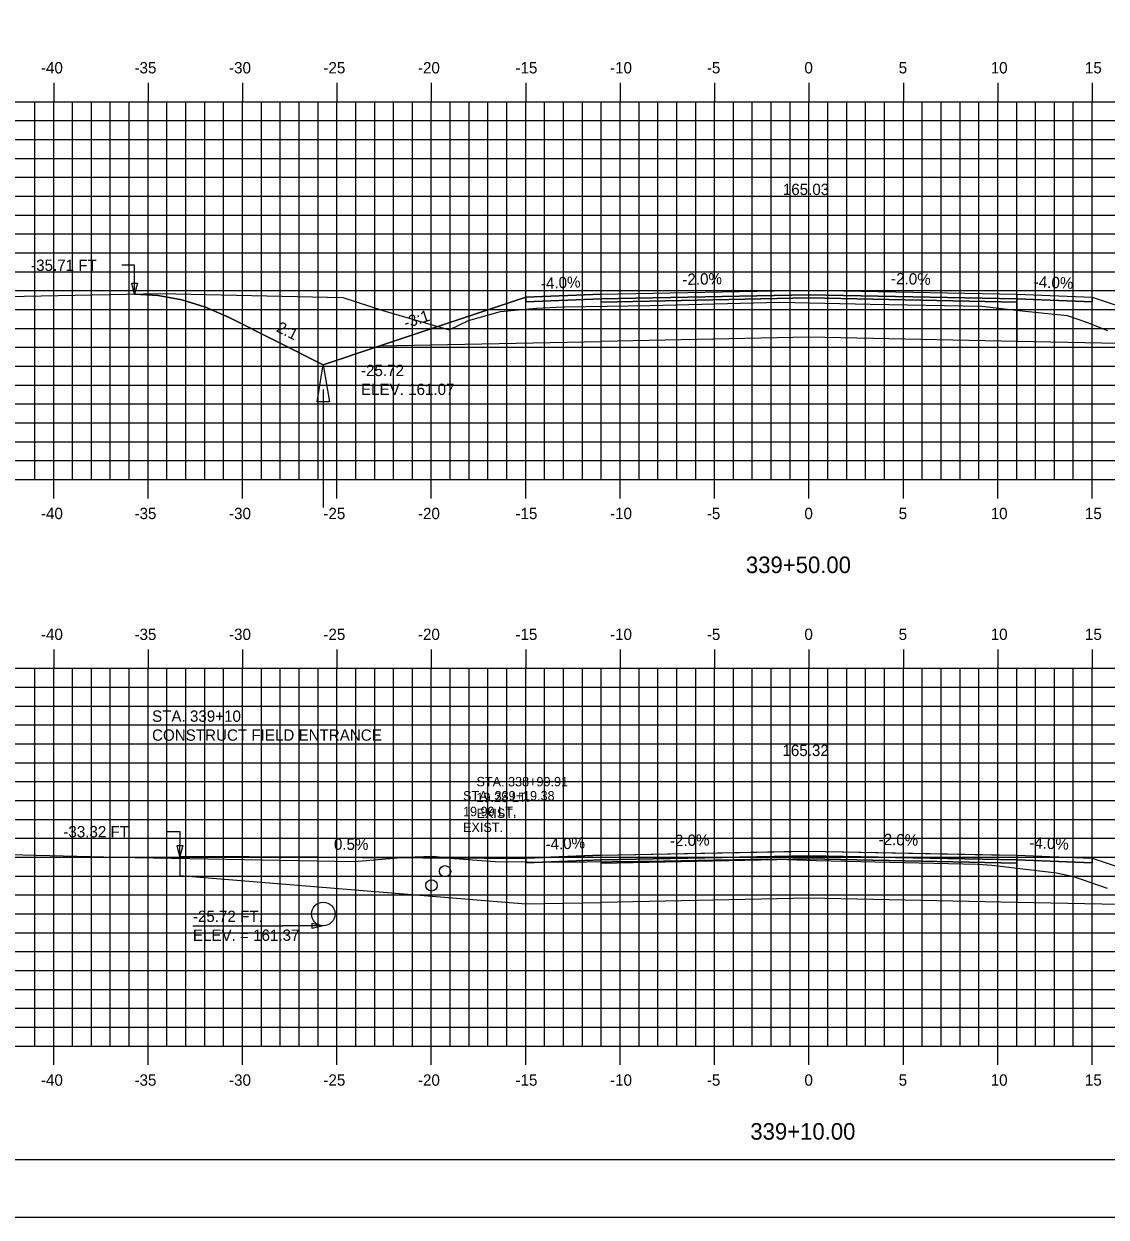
# Model space of a CAD drawing. Extents: x 1142755 to 1142925, y 608981 to 609091.
# Drawn here: x 1142796.2 to 1142853.5, y 608981.3 to 609044.5 of the extents above; entities that cross this region are included whole.
import ezdxf

# ---------------------------------------------------------------- set-up
doc = ezdxf.new("R2010")
doc.units = 0
for name, color, linetype in [('ANNOTATION', 7, 'Continuous'), ('BORDER', 7, 'Continuous'), ('D_Drainage_Culvert', 7, 'Continuous'), ('D_Drainage_Ditch_Line', 7, 'Continuous'), ('D_Roadway_Centerline', 7, 'Continuous'), ('D_Roadway_Centerline_Text', 7, 'Continuous'), ('D_Roadway_Edge_Shoulder', 7, 'Continuous'), ('D_Roadway_Edge_TW', 7, 'Continuous'), ('D_Roadway_Pavement', 7, 'Continuous'), ('D_Roadway_SlopeLines', 7, 'Continuous'), ('D_Roadway_SubGrade', 7, 'Continuous'), ('D_Text_Monospaced', 7, 'Continuous'), ('D_Text_Standard', 7, 'Continuous'), ('H_V ANNOTATION', 7, 'Continuous'), ('MAJOR', 7, 'Continuous'), ('MINOR', 7, 'Continuous'), ('PLOT BOUNDARY', 7, 'Continuous'), ('S_Drainage_Invert', 7, 'Continuous'), ('S_Roadway_Centerline', 7, 'Continuous')]:
    doc.layers.add(name, color=color, linetype=linetype)

msp = doc.modelspace()

# ---------------------------------------------------------------- linework, layer by layer
for points in [[(1142802.095, 609030.152), (1142803.345, 609030.075), (1142804.595, 609029.841), (1142805.845, 609029.451), (1142807.095, 609028.904), (1142812.085, 609026.409), (1142815.085, 609027.409), (1142822.809, 609029.983), (1142822.81, 609029.983), (1142826.81, 609030.143), (1142837.81, 609030.363), (1142848.81, 609030.143), (1142852.81, 609029.983), (1142860.533, 609027.409), (1142863.533, 609026.409), (1142866.262, 609027.773), (1142867.512, 609028.319), (1142868.762, 609028.709), (1142870.012, 609028.941), (1142871.262, 609029.016)], [(1142804.493, 609000.369), (1142820.615, 609000.288), (1142822.81, 609000.277), (1142823.29, 609000.296), (1142826.81, 609000.437), (1142836.49, 609000.631), (1142837.81, 609000.657), (1142847.49, 609000.464), (1142848.81, 609000.437), (1142852.33, 609000.296), (1142852.81, 609000.277), (1142859.606, 608998.012)]]:
    msp.add_lwpolyline(points)
at = {"layer": 'BORDER'}
msp.add_lwpolyline([(1142762.81, 608984.335), (1142922.81, 608984.335), (1142922.81, 609089.335), (1142762.81, 609089.335)], close=True, dxfattribs=at)
at = {"layer": 'D_Drainage_Culvert'}
msp.add_circle((1142812.086, 608997.328), 0.625, dxfattribs=at)
at = {"layer": 'D_Drainage_Ditch_Line'}
msp.add_line((1142812.085, 609025.097), (1142812.085, 609018.853), dxfattribs=at)
msp.add_lwpolyline([(1142812.413, 609024.44), (1142811.757, 609024.44), (1142812.085, 609026.409)], close=True, dxfattribs=at)
at = {"layer": 'D_Roadway_Edge_Shoulder'}
for points in [[(1142826.81, 609030.143), (1142822.81, 609029.983), (1142822.81, 609029.733), (1142826.81, 609029.893)], [(1142848.81, 609030.143), (1142852.81, 609029.983), (1142852.81, 609029.733), (1142848.81, 609029.893)], [(1142826.81, 609000.437), (1142822.81, 609000.277), (1142822.81, 609000.027), (1142826.81, 609000.187)], [(1142848.81, 609000.437), (1142852.81, 609000.277), (1142852.81, 609000.027), (1142848.81, 609000.187)]]:
    msp.add_lwpolyline(points, close=True, dxfattribs=at)
at = {"layer": 'D_Roadway_Edge_TW'}
for points in [[(1142826.81, 609029.893), (1142826.81, 609030.143), (1142837.81, 609030.363), (1142848.81, 609030.143), (1142848.81, 609029.893), (1142837.81, 609030.113)], [(1142826.81, 609000.187), (1142826.81, 609000.437), (1142837.81, 609000.657), (1142848.81, 609000.437), (1142848.81, 609000.187), (1142837.81, 609000.407)]]:
    msp.add_lwpolyline(points, close=True, dxfattribs=at)
at = {"layer": 'D_Roadway_Pavement'}
for points in [[(1142826.81, 609029.727), (1142826.81, 609029.893), (1142837.81, 609030.113), (1142848.81, 609029.893), (1142848.81, 609029.727), (1142837.81, 609029.947)], [(1142826.81, 609000.02), (1142826.81, 609000.187), (1142837.81, 609000.407), (1142848.81, 609000.187), (1142848.81, 609000.021), (1142837.81, 609000.241)]]:
    msp.add_lwpolyline(points, close=True, dxfattribs=at)
at = {"layer": 'D_Roadway_SlopeLines'}
for points in [[(1142812.085, 609026.409), (1142807.095, 609028.904), (1142805.845, 609029.451), (1142804.595, 609029.841), (1142803.345, 609030.075), (1142802.095, 609030.152)], [(1142815.085, 609027.409), (1142812.085, 609026.409)]]:
    msp.add_lwpolyline(points, dxfattribs=at)
at = {"layer": 'D_Roadway_SubGrade'}
for points in [[(1142826.81, 609029.727), (1142826.81, 609029.893), (1142822.81, 609029.733), (1142822.81, 609029.983), (1142822.809, 609029.983), (1142815.085, 609027.409), (1142826.81, 609027.643)], [(1142826.81, 609027.643), (1142826.81, 609029.727), (1142837.81, 609029.947), (1142848.81, 609029.727), (1142848.81, 609027.643), (1142837.81, 609027.863)], [(1142848.81, 609029.727), (1142848.81, 609029.893), (1142852.81, 609029.733), (1142852.81, 609029.983), (1142852.81, 609029.983), (1142860.533, 609027.409), (1142848.81, 609027.643)], [(1142804.493, 608999.369), (1142822.81, 608997.857), (1142826.81, 608997.937), (1142826.81, 609000.02), (1142826.81, 609000.187), (1142822.81, 609000.027), (1142822.81, 609000.277), (1142804.493, 609000.369)], [(1142826.81, 608997.937), (1142826.81, 609000.02), (1142837.81, 609000.241), (1142848.81, 609000.021), (1142848.81, 608997.937), (1142837.81, 608998.157)], [(1142848.81, 609000.021), (1142848.81, 609000.187), (1142852.81, 609000.027), (1142852.81, 609000.277), (1142852.81, 609000.277), (1142860.533, 608997.703), (1142848.81, 608997.937)]]:
    msp.add_lwpolyline(points, close=True, dxfattribs=at)
at = {"layer": 'D_Text_Standard'}
msp.add_line((1142805.182, 608996.703), (1142809.94, 608996.703), dxfattribs=at)
for points in [[(1142802.095, 609030.154), (1142802.097, 609031.677), (1142801.417, 609031.677)], [(1142804.493, 609000.369), (1142804.5, 609001.684), (1142803.82, 609001.684)], [(1142812.086, 608996.703), (1142810.62, 608996.703), (1142809.94, 608996.703)]]:
    msp.add_lwpolyline(points, dxfattribs=at)
for points in [[(1142802.095, 609030.154), (1142801.95, 609030.736), (1142802.241, 609030.736)], [(1142804.493, 609000.369), (1142804.35, 609000.952), (1142804.641, 609000.95)], [(1142812.086, 608996.703), (1142811.504, 608996.557), (1142811.504, 608996.848)]]:
    msp.add_lwpolyline(points, close=True, dxfattribs=at)
at = {"layer": 'MAJOR'}
for p, q in [((1142797.81, 609041.337), (1142797.81, 609040.335)), ((1142802.81, 609041.337), (1142802.81, 609040.335)), ((1142807.81, 609041.337), (1142807.81, 609040.335)), ((1142812.81, 609041.337), (1142812.81, 609040.335)), ((1142817.81, 609041.337), (1142817.81, 609040.335)), ((1142822.81, 609041.337), (1142822.81, 609040.335)), ((1142827.81, 609041.337), (1142827.81, 609040.335)), ((1142832.81, 609041.337), (1142832.81, 609040.335)), ((1142837.81, 609041.337), (1142837.81, 609040.335)), ((1142842.81, 609041.337), (1142842.81, 609040.335)), ((1142847.81, 609041.337), (1142847.81, 609040.335)), ((1142852.81, 609041.337), (1142852.81, 609040.335)), ((1142767.81, 609040.335), (1142907.81, 609040.335)), ((1142767.81, 609040.335), (1142907.81, 609040.335)), ((1142797.81, 609020.335), (1142797.81, 609040.335)), ((1142802.81, 609020.335), (1142802.81, 609040.335)), ((1142807.81, 609020.335), (1142807.81, 609040.335)), ((1142812.81, 609020.335), (1142812.81, 609040.335)), ((1142817.81, 609020.335), (1142817.81, 609040.335)), ((1142822.81, 609020.335), (1142822.81, 609040.335)), ((1142827.81, 609020.335), (1142827.81, 609040.335)), ((1142832.81, 609020.335), (1142832.81, 609040.335)), ((1142837.81, 609020.335), (1142837.81, 609040.335)), ((1142842.81, 609020.335), (1142842.81, 609040.335)), ((1142847.81, 609020.335), (1142847.81, 609040.335)), ((1142852.81, 609020.335), (1142852.81, 609040.335)), ((1142767.81, 609035.335), (1142907.81, 609035.335)), ((1142767.81, 609030.335), (1142907.81, 609030.335)), ((1142767.81, 609025.335), (1142907.81, 609025.335)), ((1142767.81, 609020.335), (1142907.81, 609020.335)), ((1142767.81, 609020.335), (1142907.81, 609020.335)), ((1142797.81, 609019.333), (1142797.81, 609020.335)), ((1142802.81, 609019.333), (1142802.81, 609020.335)), ((1142807.81, 609019.333), (1142807.81, 609020.335)), ((1142812.81, 609019.333), (1142812.81, 609020.335)), ((1142817.81, 609019.333), (1142817.81, 609020.335)), ((1142822.81, 609019.333), (1142822.81, 609020.335)), ((1142827.81, 609019.333), (1142827.81, 609020.335)), ((1142832.81, 609019.333), (1142832.81, 609020.335)), ((1142837.81, 609019.333), (1142837.81, 609020.335)), ((1142842.81, 609019.333), (1142842.81, 609020.335)), ((1142847.81, 609019.333), (1142847.81, 609020.335)), ((1142852.81, 609019.333), (1142852.81, 609020.335)), ((1142797.81, 609011.337), (1142797.81, 609010.335)), ((1142802.81, 609011.337), (1142802.81, 609010.335)), ((1142807.81, 609011.337), (1142807.81, 609010.335)), ((1142812.81, 609011.337), (1142812.81, 609010.335)), ((1142817.81, 609011.337), (1142817.81, 609010.335)), ((1142822.81, 609011.337), (1142822.81, 609010.335)), ((1142827.81, 609011.337), (1142827.81, 609010.335)), ((1142832.81, 609011.337), (1142832.81, 609010.335)), ((1142837.81, 609011.337), (1142837.81, 609010.335)), ((1142842.81, 609011.337), (1142842.81, 609010.335)), ((1142847.81, 609011.337), (1142847.81, 609010.335)), ((1142852.81, 609011.337), (1142852.81, 609010.335)), ((1142767.81, 609010.335), (1142907.81, 609010.335)), ((1142767.81, 609010.335), (1142907.81, 609010.335)), ((1142797.81, 608990.335), (1142797.81, 609010.335)), ((1142802.81, 608990.335), (1142802.81, 609010.335)), ((1142807.81, 608990.335), (1142807.81, 609010.335)), ((1142812.81, 608990.335), (1142812.81, 609010.335)), ((1142817.81, 608990.335), (1142817.81, 609010.335)), ((1142822.81, 608990.335), (1142822.81, 609010.335)), ((1142827.81, 608990.335), (1142827.81, 609010.335)), ((1142832.81, 608990.335), (1142832.81, 609010.335)), ((1142837.81, 608990.335), (1142837.81, 609010.335)), ((1142842.81, 608990.335), (1142842.81, 609010.335)), ((1142847.81, 608990.335), (1142847.81, 609010.335)), ((1142852.81, 608990.335), (1142852.81, 609010.335)), ((1142767.81, 609005.335), (1142907.81, 609005.335)), ((1142767.81, 609000.335), (1142907.81, 609000.335)), ((1142767.81, 608995.335), (1142907.81, 608995.335)), ((1142767.81, 608990.335), (1142907.81, 608990.335)), ((1142767.81, 608990.335), (1142907.81, 608990.335)), ((1142797.81, 608989.333), (1142797.81, 608990.335)), ((1142802.81, 608989.333), (1142802.81, 608990.335)), ((1142807.81, 608989.333), (1142807.81, 608990.335)), ((1142812.81, 608989.333), (1142812.81, 608990.335)), ((1142817.81, 608989.333), (1142817.81, 608990.335)), ((1142822.81, 608989.333), (1142822.81, 608990.335)), ((1142827.81, 608989.333), (1142827.81, 608990.335)), ((1142832.81, 608989.333), (1142832.81, 608990.335)), ((1142837.81, 608989.333), (1142837.81, 608990.335)), ((1142842.81, 608989.333), (1142842.81, 608990.335)), ((1142847.81, 608989.333), (1142847.81, 608990.335)), ((1142852.81, 608989.333), (1142852.81, 608990.335))]:
    msp.add_line(p, q, dxfattribs=at)
at = {"layer": 'MINOR'}
for p, q in [((1142796.81, 609020.335), (1142796.81, 609040.335)), ((1142798.81, 609020.335), (1142798.81, 609040.335)), ((1142799.81, 609020.335), (1142799.81, 609040.335)), ((1142800.81, 609020.335), (1142800.81, 609040.335)), ((1142801.81, 609020.335), (1142801.81, 609040.335)), ((1142803.81, 609020.335), (1142803.81, 609040.335)), ((1142804.81, 609020.335), (1142804.81, 609040.335)), ((1142805.81, 609020.335), (1142805.81, 609040.335)), ((1142806.81, 609020.335), (1142806.81, 609040.335)), ((1142808.81, 609020.335), (1142808.81, 609040.335)), ((1142809.81, 609020.335), (1142809.81, 609040.335)), ((1142810.81, 609020.335), (1142810.81, 609040.335)), ((1142811.81, 609020.335), (1142811.81, 609040.335)), ((1142813.81, 609020.335), (1142813.81, 609040.335)), ((1142814.81, 609020.335), (1142814.81, 609040.335)), ((1142815.81, 609020.335), (1142815.81, 609040.335)), ((1142816.81, 609020.335), (1142816.81, 609040.335)), ((1142818.81, 609020.335), (1142818.81, 609040.335)), ((1142819.81, 609020.335), (1142819.81, 609040.335)), ((1142820.81, 609020.335), (1142820.81, 609040.335)), ((1142821.81, 609020.335), (1142821.81, 609040.335)), ((1142823.81, 609020.335), (1142823.81, 609040.335)), ((1142824.81, 609020.335), (1142824.81, 609040.335)), ((1142825.81, 609020.335), (1142825.81, 609040.335)), ((1142826.81, 609020.335), (1142826.81, 609040.335)), ((1142828.81, 609020.335), (1142828.81, 609040.335)), ((1142829.81, 609020.335), (1142829.81, 609040.335)), ((1142830.81, 609020.335), (1142830.81, 609040.335)), ((1142831.81, 609020.335), (1142831.81, 609040.335)), ((1142833.81, 609020.335), (1142833.81, 609040.335)), ((1142834.81, 609020.335), (1142834.81, 609040.335)), ((1142835.81, 609020.335), (1142835.81, 609040.335)), ((1142836.81, 609020.335), (1142836.81, 609040.335)), ((1142838.81, 609020.335), (1142838.81, 609040.335)), ((1142839.81, 609020.335), (1142839.81, 609040.335)), ((1142840.81, 609020.335), (1142840.81, 609040.335)), ((1142841.81, 609020.335), (1142841.81, 609040.335)), ((1142843.81, 609020.335), (1142843.81, 609040.335)), ((1142844.81, 609020.335), (1142844.81, 609040.335)), ((1142845.81, 609020.335), (1142845.81, 609040.335)), ((1142846.81, 609020.335), (1142846.81, 609040.335)), ((1142848.81, 609020.335), (1142848.81, 609040.335)), ((1142849.81, 609020.335), (1142849.81, 609040.335)), ((1142850.81, 609020.335), (1142850.81, 609040.335)), ((1142851.81, 609020.335), (1142851.81, 609040.335)), ((1142767.81, 609039.335), (1142907.81, 609039.335)), ((1142767.81, 609038.335), (1142907.81, 609038.335)), ((1142767.81, 609037.335), (1142907.81, 609037.335)), ((1142767.81, 609036.335), (1142907.81, 609036.335)), ((1142767.81, 609034.335), (1142907.81, 609034.335)), ((1142767.81, 609033.335), (1142907.81, 609033.335)), ((1142767.81, 609032.335), (1142907.81, 609032.335)), ((1142767.81, 609031.335), (1142907.81, 609031.335)), ((1142767.81, 609029.335), (1142907.81, 609029.335)), ((1142767.81, 609028.335), (1142907.81, 609028.335)), ((1142767.81, 609027.335), (1142907.81, 609027.335)), ((1142767.81, 609026.335), (1142907.81, 609026.335)), ((1142767.81, 609024.335), (1142907.81, 609024.335)), ((1142767.81, 609023.335), (1142907.81, 609023.335)), ((1142767.81, 609022.335), (1142907.81, 609022.335)), ((1142767.81, 609021.335), (1142907.81, 609021.335)), ((1142796.81, 608990.335), (1142796.81, 609010.335)), ((1142798.81, 608990.335), (1142798.81, 609010.335)), ((1142799.81, 608990.335), (1142799.81, 609010.335)), ((1142800.81, 608990.335), (1142800.81, 609010.335)), ((1142801.81, 608990.335), (1142801.81, 609010.335)), ((1142803.81, 608990.335), (1142803.81, 609010.335)), ((1142804.81, 608990.335), (1142804.81, 609010.335)), ((1142805.81, 608990.335), (1142805.81, 609010.335)), ((1142806.81, 608990.335), (1142806.81, 609010.335)), ((1142808.81, 608990.335), (1142808.81, 609010.335)), ((1142809.81, 608990.335), (1142809.81, 609010.335)), ((1142810.81, 608990.335), (1142810.81, 609010.335)), ((1142811.81, 608990.335), (1142811.81, 609010.335)), ((1142813.81, 608990.335), (1142813.81, 609010.335)), ((1142814.81, 608990.335), (1142814.81, 609010.335)), ((1142815.81, 608990.335), (1142815.81, 609010.335)), ((1142816.81, 608990.335), (1142816.81, 609010.335)), ((1142818.81, 608990.335), (1142818.81, 609010.335)), ((1142819.81, 608990.335), (1142819.81, 609010.335)), ((1142820.81, 608990.335), (1142820.81, 609010.335)), ((1142821.81, 608990.335), (1142821.81, 609010.335)), ((1142823.81, 608990.335), (1142823.81, 609010.335)), ((1142824.81, 608990.335), (1142824.81, 609010.335)), ((1142825.81, 608990.335), (1142825.81, 609010.335)), ((1142826.81, 608990.335), (1142826.81, 609010.335)), ((1142828.81, 608990.335), (1142828.81, 609010.335)), ((1142829.81, 608990.335), (1142829.81, 609010.335)), ((1142830.81, 608990.335), (1142830.81, 609010.335)), ((1142831.81, 608990.335), (1142831.81, 609010.335)), ((1142833.81, 608990.335), (1142833.81, 609010.335)), ((1142834.81, 608990.335), (1142834.81, 609010.335)), ((1142835.81, 608990.335), (1142835.81, 609010.335)), ((1142836.81, 608990.335), (1142836.81, 609010.335)), ((1142838.81, 608990.335), (1142838.81, 609010.335)), ((1142839.81, 608990.335), (1142839.81, 609010.335)), ((1142840.81, 608990.335), (1142840.81, 609010.335)), ((1142841.81, 608990.335), (1142841.81, 609010.335)), ((1142843.81, 608990.335), (1142843.81, 609010.335)), ((1142844.81, 608990.335), (1142844.81, 609010.335)), ((1142845.81, 608990.335), (1142845.81, 609010.335)), ((1142846.81, 608990.335), (1142846.81, 609010.335)), ((1142848.81, 608990.335), (1142848.81, 609010.335)), ((1142849.81, 608990.335), (1142849.81, 609010.335)), ((1142850.81, 608990.335), (1142850.81, 609010.335)), ((1142851.81, 608990.335), (1142851.81, 609010.335)), ((1142767.81, 609009.335), (1142907.81, 609009.335)), ((1142767.81, 609008.335), (1142907.81, 609008.335)), ((1142767.81, 609007.335), (1142907.81, 609007.335)), ((1142767.81, 609006.335), (1142907.81, 609006.335)), ((1142767.81, 609004.335), (1142907.81, 609004.335)), ((1142767.81, 609003.335), (1142907.81, 609003.335)), ((1142767.81, 609002.335), (1142907.81, 609002.335)), ((1142767.81, 609001.335), (1142907.81, 609001.335)), ((1142767.81, 608999.335), (1142907.81, 608999.335)), ((1142767.81, 608998.335), (1142907.81, 608998.335)), ((1142767.81, 608997.335), (1142907.81, 608997.335)), ((1142767.81, 608996.335), (1142907.81, 608996.335)), ((1142767.81, 608994.335), (1142907.81, 608994.335)), ((1142767.81, 608993.335), (1142907.81, 608993.335)), ((1142767.81, 608992.335), (1142907.81, 608992.335)), ((1142767.81, 608991.335), (1142907.81, 608991.335))]:
    msp.add_line(p, q, dxfattribs=at)
at = {"layer": 'PLOT BOUNDARY'}
msp.add_lwpolyline([(1142754.717, 608981.276), (1142924.717, 608981.276), (1142924.717, 609091.276), (1142754.717, 609091.276)], close=True, dxfattribs=at)
at = {"layer": 'S_Drainage_Invert'}
for centre in [(1142818.535, 608999.586), (1142817.821, 608998.84)]:
    msp.add_circle(centre, 0.3, dxfattribs=at)
at = {"layer": 'S_Roadway_Centerline'}
for points in [[(1142767.81, 609029.872), (1142772.659, 609029.903), (1142789.902, 609029.91), (1142803.459, 609030.179), (1142813.124, 609029.964), (1142815.249, 609029.282), (1142818.76, 609028.26), (1142819.78, 609028.76), (1142821.467, 609029.225), (1142823.377, 609029.407), (1142824.778, 609029.469), (1142824.866, 609029.472), (1142829.375, 609029.546), (1142836.25, 609029.718), (1142841.052, 609029.61), (1142846.97, 609029.506), (1142848.923, 609029.281), (1142851.479, 609029.02), (1142852.506, 609028.667), (1142853.62, 609028.219)], [(1142767.81, 609000.492), (1142769.72, 609000.472), (1142791.868, 609000.571), (1142801.171, 609000.338), (1142812.704, 609000.117), (1142813.716, 609000.114), (1142816.434, 609000.342), (1142817.916, 609000.395), (1142819.044, 609000.26), (1142821.193, 609000.108), (1142822.89, 609000.096), (1142824.694, 609000.064), (1142830.108, 609000.149), (1142835.615, 609000.249), (1142838.206, 609000.162), (1142846.754, 608999.969), (1142847.489, 608999.907), (1142850.927, 608999.511), (1142851.828, 608999.305), (1142853.607, 608998.697)]]:
    msp.add_lwpolyline(points, dxfattribs=at)

# ---------------------------------------------------------------- texts
at = {"layer": 'ANNOTATION'}
for s, rotation, p in [('-4.0%', 2.29061, (1142823.626, 609030.417)), ('-2.0%', 1.14576, (1142831.113, 609030.63)), ('-2.0%', 358.85424, (1142842.153, 609030.677)), ('-4.0%', 357.70939, (1142849.706, 609030.508)), ('-3:1', 18.43482, (1142816.464, 609028.323)), ('2:1', 333.43495, (1142809.557, 609028.191)), ('0.5%', 359.71352, (1142812.65, 609000.728)), ('-4.0%', 2.29061, (1142823.866, 609000.72)), ('-2.0%', 1.14576, (1142830.453, 609000.91)), ('-2.0%', 358.85424, (1142841.493, 609000.984)), ('-4.0%', 357.70939, (1142849.466, 609000.812))]:
    msp.add_text(s, height=0.6, rotation=rotation, dxfattribs=at).set_placement(p)
for s, p in [('STA. 339+10', (1142803.02, 609007.503)), ('CONSTRUCT FIELD ENTRANCE', (1142803.02, 609006.501))]:
    msp.add_text(s, height=0.6, dxfattribs=at).set_placement(p)
at = {"layer": 'D_Roadway_Centerline'}
for s, p in [('C', (1142837.805, 609030.363)), ('L', (1142837.81, 609030.356)), ('C', (1142837.805, 609000.657)), ('L', (1142837.81, 609000.65))]:
    msp.add_text(s, height=0.0146, dxfattribs=at).set_placement(p)
at = {"layer": 'D_Roadway_Centerline_Text'}
for s, p in [('165.03', (1142836.427, 609035.395)), ('165.32', (1142836.405, 609005.689))]:
    msp.add_text(s, height=0.6, dxfattribs=at).set_placement(p)
at = {"layer": 'D_Text_Monospaced'}
for s, height, p in [('STA. 338+99.91', 0.49998, (1142820.201, 609004.084)), ('STA. 339+19.38', 0.49998, (1142819.488, 609003.338)), ('19.28 LT.', 0.5, (1142820.201, 609003.25)), ('19.99 LT.', 0.5, (1142819.488, 609002.504)), ('EXIST. ', 0.5, (1142820.201, 609002.41)), ('EXIST. ', 0.5, (1142819.488, 609001.664))]:
    msp.add_text(s, height=height, dxfattribs=at).set_placement(p)
at = {"layer": 'D_Text_Standard'}
for s, p in [('-35.71 FT', (1142796.615, 609031.377)), ('-25.72', (1142814.085, 609025.809)), ('ELEV. 161.07', (1142814.085, 609024.807)), ('-33.32 FT', (1142798.322, 609001.384)), ('-25.72 FT.', (1142805.182, 608996.903)), ('ELEV. = 161.37', (1142805.182, 608995.903))]:
    msp.add_text(s, height=0.6, dxfattribs=at).set_placement(p)
at = {"layer": 'H_V ANNOTATION'}
for s, height, p in [('-40', 0.6, (1142797.136, 609041.835)), ('-35', 0.6, (1142802.09, 609041.835)), ('-30', 0.6, (1142807.098, 609041.835)), ('-25', 0.6, (1142812.095, 609041.835)), ('-20', 0.6, (1142817.103, 609041.835)), ('-15', 0.6, (1142822.267, 609041.835)), ('-10', 0.6, (1142827.275, 609041.835)), ('-5', 0.6, (1142832.401, 609041.835)), ('0', 0.6, (1142837.569, 609041.835)), ('5', 0.6, (1142842.561, 609041.835)), ('10', 0.6, (1142847.435, 609041.835)), ('15', 0.6, (1142852.427, 609041.835)), ('-40', 0.6, (1142797.136, 609018.235)), ('-35', 0.6, (1142802.09, 609018.235)), ('-30', 0.6, (1142807.098, 609018.235)), ('-25', 0.6, (1142812.095, 609018.235)), ('-20', 0.6, (1142817.103, 609018.235)), ('-15', 0.6, (1142822.267, 609018.235)), ('-10', 0.6, (1142827.275, 609018.235)), ('-5', 0.6, (1142832.401, 609018.235)), ('0', 0.6, (1142837.569, 609018.235)), ('5', 0.6, (1142842.561, 609018.235)), ('10', 0.6, (1142847.435, 609018.235)), ('15', 0.6, (1142852.427, 609018.235)), ('339+50.00', 0.875, (1142834.47, 609015.378)), ('-40', 0.6, (1142797.136, 609011.835)), ('-35', 0.6, (1142802.09, 609011.835)), ('-30', 0.6, (1142807.098, 609011.835)), ('-25', 0.6, (1142812.095, 609011.835)), ('-20', 0.6, (1142817.103, 609011.835)), ('-15', 0.6, (1142822.267, 609011.835)), ('-10', 0.6, (1142827.275, 609011.835)), ('-5', 0.6, (1142832.401, 609011.835)), ('0', 0.6, (1142837.569, 609011.835)), ('5', 0.6, (1142842.561, 609011.835)), ('10', 0.6, (1142847.435, 609011.835)), ('15', 0.6, (1142852.427, 609011.835)), ('-40', 0.6, (1142797.136, 608988.235)), ('-35', 0.6, (1142802.09, 608988.235)), ('-30', 0.6, (1142807.098, 608988.235)), ('-25', 0.6, (1142812.095, 608988.235)), ('-20', 0.6, (1142817.103, 608988.235)), ('-15', 0.6, (1142822.267, 608988.235)), ('-10', 0.6, (1142827.275, 608988.235)), ('-5', 0.6, (1142832.401, 608988.235)), ('0', 0.6, (1142837.569, 608988.235)), ('5', 0.6, (1142842.561, 608988.235)), ('10', 0.6, (1142847.435, 608988.235)), ('15', 0.6, (1142852.427, 608988.235)), ('339+10.00', 0.875, (1142834.705, 608985.378))]:
    msp.add_text(s, height=height, dxfattribs=at).set_placement(p)
at = {"layer": 'S_Roadway_Centerline'}
for s, p in [('L', (1142836.242, 609029.711)), ('C', (1142836.245, 609029.718)), ('L', (1142835.606, 609000.242)), ('C', (1142835.61, 609000.249))]:
    msp.add_text(s, height=0.0146, dxfattribs=at).set_placement(p)

doc.saveas('drawing.dxf')
